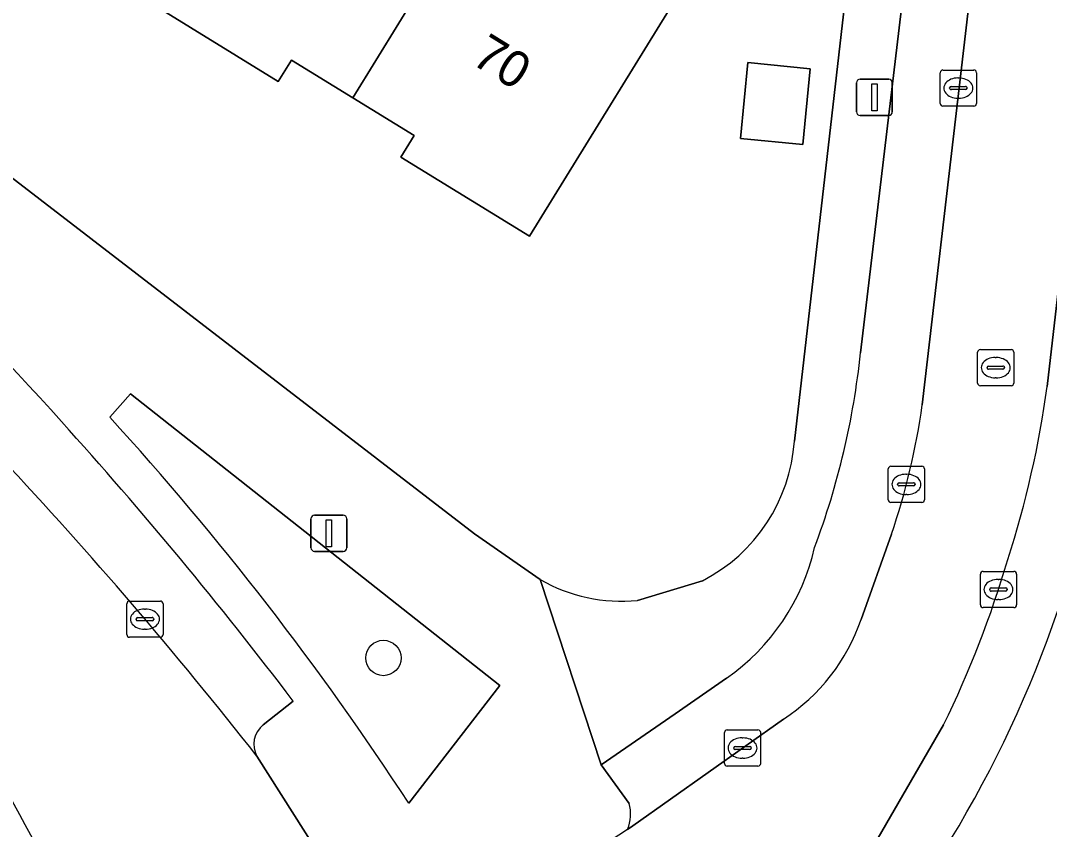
# Model space of a CAD drawing. Extents: x 161692 to 162379, y 380760 to 381678.
# Drawn here: x 161919.85 to 161948.28, y 381006.21 to 381028.56 of the extents above; entities that cross this region are included whole.
import ezdxf

# ---------------------------------------------------------------- set-up
doc = ezdxf.new("R2010")
doc.units = 0
for name, color, linetype in [('IMGEO_Boom', 7, 'Continuous'), ('IMGEO_Erf', 7, 'Continuous'), ('IMGEO_Groenvoorziening', 7, 'Continuous'), ('IMGEO_Kolk', 7, 'Continuous'), ('IMGEO_Lichtmast', 7, 'Continuous'), ('IMGEO_Pand', 7, 'Continuous'), ('IMGEO_Pand_nummerreeks', 7, 'Continuous'), ('IMGEO_Parkeervlak_open', 7, 'Continuous'), ('IMGEO_Rijbaan_lokaal_open', 7, 'Continuous'), ('IMGEO_Rioolput', 7, 'Continuous'), ('IMGEO_Voetpad_open', 7, 'Continuous')]:
    doc.layers.add(name, color=color, linetype=linetype)

msp = doc.modelspace()

# ---------------------------------------------------------------- linework, layer by layer
at = {"layer": 'IMGEO_Boom'}
msp.add_circle((161929.874, 381010.946), 0.489, dxfattribs=at)
at = {"layer": 'IMGEO_Erf'}
for points in [[(161941.233, 381016.938), (161944.934, 381049.22)], [(161918.09, 381043.966), (161920.768, 381042.317), (161920.378, 381041.684), (161922.995, 381040.073), (161925.41, 381038.587), (161926.13, 381039.756), (161928.914, 381038.042), (161934.18, 381034.801), (161934.766, 381035.752), (161940.015, 381032.521), (161938.727, 381030.429), (161933.91, 381022.602), (161930.356, 381024.789), (161930.723, 381025.385), (161929.03, 381026.427), (161927.333, 381027.472), (161926.969, 381026.881), (161923.395, 381029.081), (161919.818, 381031.283), (161920.176, 381031.865), (161918.558, 381032.86)], [(161916.42, 381026.67), (161932.395, 381014.373), (161934.208, 381013.114)], [(161936.895, 381012.539), (161938.695, 381013.082)]]:
    msp.add_lwpolyline(points, dxfattribs=at)
msp.add_lwpolyline([(161941.669, 381027.23), (161941.462, 381025.139), (161939.739, 381025.309), (161939.946, 381027.401)], close=True, dxfattribs=at)
for centre, radius, start, end in [((161936.529, 381017.271), 4.715, 297.3406, 355.954), ((161936.451, 381017.031), 4.514, 240.2007, 275.6418)]:
    msp.add_arc(centre, radius, start, end, dxfattribs=at)
at = {"layer": 'IMGEO_Groenvoorziening'}
msp.add_lwpolyline([(161930.575, 381006.93), (161933.096, 381010.186), (161922.886, 381018.248), (161922.313, 381017.602)], dxfattribs=at)
msp.add_arc((161860.947, 380961.56), 83.105, 33.08857, 42.40374, dxfattribs=at)
at = {"layer": 'IMGEO_Kolk'}
for p, q in [((161945.26, 381026.272), (161945.26, 381027.124)), ((161945.335, 381027.198), (161946.187, 381027.198)), ((161946.261, 381027.124), (161946.261, 381026.272)), ((161945.519, 381026.692), (161945.519, 381026.704)), ((161945.562, 381026.741), (161945.96, 381026.741)), ((161945.748, 381026.978), (161945.773, 381026.978)), ((161946.003, 381026.704), (161946.003, 381026.692)), ((161945.957, 381026.655), (161945.559, 381026.655)), ((161945.771, 381026.418), (161945.746, 381026.418)), ((161946.187, 381026.198), (161945.335, 381026.198)), ((161943.899, 381016.244), (161944.751, 381016.244)), ((161943.824, 381015.318), (161943.824, 381016.17)), ((161944.312, 381016.024), (161944.337, 381016.024)), ((161944.825, 381016.17), (161944.825, 381015.318)), ((161944.083, 381015.738), (161944.083, 381015.75)), ((161944.521, 381015.701), (161944.123, 381015.701)), ((161944.126, 381015.787), (161944.524, 381015.787)), ((161944.567, 381015.75), (161944.567, 381015.738)), ((161944.335, 381015.464), (161944.31, 381015.464)), ((161944.751, 381015.244), (161943.899, 381015.244)), ((161946.443, 381013.338), (161947.295, 381013.338)), ((161946.368, 381012.412), (161946.368, 381013.264)), ((161946.856, 381013.118), (161946.881, 381013.118)), ((161947.369, 381013.264), (161947.369, 381012.412)), ((161946.627, 381012.832), (161946.627, 381012.844)), ((161947.065, 381012.795), (161946.667, 381012.795)), ((161946.67, 381012.881), (161947.068, 381012.881)), ((161947.111, 381012.844), (161947.111, 381012.832)), ((161922.861, 381012.519), (161923.713, 381012.519)), ((161946.879, 381012.558), (161946.854, 381012.558)), ((161922.786, 381011.593), (161922.786, 381012.445)), ((161923.274, 381012.299), (161923.299, 381012.299)), ((161923.787, 381012.445), (161923.787, 381011.593)), ((161947.295, 381012.338), (161946.443, 381012.338)), ((161923.045, 381012.013), (161923.045, 381012.025)), ((161923.483, 381011.976), (161923.085, 381011.976)), ((161923.088, 381012.062), (161923.486, 381012.062)), ((161923.529, 381012.025), (161923.529, 381012.013)), ((161923.297, 381011.739), (161923.272, 381011.739)), ((161923.713, 381011.519), (161922.861, 381011.519)), ((161939.297, 381008.031), (161939.297, 381008.883)), ((161939.372, 381008.957), (161940.224, 381008.957)), ((161940.298, 381008.883), (161940.298, 381008.031)), ((161939.785, 381008.737), (161939.81, 381008.737)), ((161939.556, 381008.451), (161939.556, 381008.463)), ((161939.994, 381008.414), (161939.596, 381008.414)), ((161939.599, 381008.5), (161939.997, 381008.5)), ((161940.04, 381008.463), (161940.04, 381008.451)), ((161940.224, 381007.957), (161939.372, 381007.957)), ((161939.808, 381008.177), (161939.783, 381008.177))]:
    msp.add_line(p, q, dxfattribs=at)
for points in [[(161945.26, 381026.272), (161945.26, 381027.124)], [(161945.335, 381027.198), (161946.187, 381027.198)], [(161946.261, 381027.124), (161946.261, 381026.272)], [(161946.187, 381026.198), (161945.335, 381026.198)], [(161943.899, 381016.244), (161944.751, 381016.244)], [(161943.824, 381015.318), (161943.824, 381016.17)], [(161944.825, 381016.17), (161944.825, 381015.318)], [(161944.751, 381015.244), (161943.899, 381015.244)], [(161946.443, 381013.338), (161947.295, 381013.338)], [(161946.368, 381012.412), (161946.368, 381013.264)], [(161947.369, 381013.264), (161947.369, 381012.412)], [(161922.861, 381012.519), (161923.713, 381012.519)], [(161922.786, 381011.593), (161922.786, 381012.445)], [(161923.787, 381012.445), (161923.787, 381011.593)], [(161947.295, 381012.338), (161946.443, 381012.338)], [(161923.713, 381011.519), (161922.861, 381011.519)], [(161939.297, 381008.031), (161939.297, 381008.883)], [(161939.372, 381008.957), (161940.224, 381008.957)], [(161940.298, 381008.883), (161940.298, 381008.031)], [(161940.224, 381007.957), (161939.372, 381007.957)]]:
    msp.add_lwpolyline(points, dxfattribs=at)
for centre, radius, start, end in [((161945.337, 381027.122), 0.0765, 91.552, 178.448), ((161945.337, 381027.122), 0.0765, 91.552, 178.448), ((161946.185, 381027.122), 0.0765, 1.552, 88.448), ((161946.185, 381027.122), 0.0765, 1.552, 88.448), ((161945.559, 381026.701), 0.0403, 85.8775, 175.7526), ((161945.964, 381026.703), 0.0386, 1.7309, 96.639), ((161945.556, 381026.691), 0.0366, 178.938, 274.7102), ((161945.96, 381026.698), 0.043, 264.8664, 352.4533), ((161945.337, 381026.274), 0.0765, 181.552, 268.448), ((161945.337, 381026.274), 0.0765, 181.552, 268.448), ((161946.185, 381026.274), 0.0765, 271.552, 358.448), ((161946.185, 381026.274), 0.0765, 271.552, 358.448), ((161943.901, 381016.168), 0.0765, 91.552, 178.448), ((161943.901, 381016.168), 0.0765, 91.552, 178.448), ((161944.749, 381016.168), 0.0765, 1.552, 88.448), ((161944.749, 381016.168), 0.0765, 1.552, 88.448), ((161944.123, 381015.747), 0.0403, 85.8775, 175.7526), ((161944.12, 381015.737), 0.0366, 178.938, 274.7102), ((161944.524, 381015.744), 0.043, 264.8664, 352.4533), ((161944.528, 381015.749), 0.0386, 1.7309, 96.639), ((161943.901, 381015.32), 0.0765, 181.552, 268.448), ((161943.901, 381015.32), 0.0765, 181.552, 268.448), ((161944.749, 381015.32), 0.0765, 271.552, 358.448), ((161944.749, 381015.32), 0.0765, 271.552, 358.448), ((161946.445, 381013.262), 0.0765, 91.552, 178.448), ((161946.445, 381013.262), 0.0765, 91.552, 178.448), ((161947.293, 381013.262), 0.0765, 1.552, 88.448), ((161947.293, 381013.262), 0.0765, 1.552, 88.448), ((161946.667, 381012.841), 0.0403, 85.8775, 175.7526), ((161946.664, 381012.831), 0.0366, 178.938, 274.7102), ((161947.068, 381012.838), 0.043, 264.8664, 352.4533), ((161947.072, 381012.843), 0.0386, 1.7309, 96.639), ((161922.863, 381012.443), 0.0765, 91.552, 178.448), ((161922.863, 381012.443), 0.0765, 91.552, 178.448), ((161923.711, 381012.443), 0.0765, 1.552, 88.448), ((161923.711, 381012.443), 0.0765, 1.552, 88.448), ((161946.445, 381012.414), 0.0765, 181.552, 268.448), ((161946.445, 381012.414), 0.0765, 181.552, 268.448), ((161947.293, 381012.414), 0.0765, 271.552, 358.448), ((161947.293, 381012.414), 0.0765, 271.552, 358.448), ((161923.085, 381012.022), 0.0403, 85.8775, 175.7526), ((161923.082, 381012.012), 0.0366, 178.938, 274.7102), ((161923.486, 381012.019), 0.043, 264.8664, 352.4533), ((161923.49, 381012.024), 0.0386, 1.7309, 96.639), ((161922.863, 381011.595), 0.0765, 181.552, 268.448), ((161922.863, 381011.595), 0.0765, 181.552, 268.448), ((161923.711, 381011.595), 0.0765, 271.552, 358.448), ((161923.711, 381011.595), 0.0765, 271.552, 358.448), ((161939.374, 381008.881), 0.0765, 91.552, 178.448), ((161939.374, 381008.881), 0.0765, 91.552, 178.448), ((161940.222, 381008.881), 0.0765, 1.552, 88.448), ((161940.222, 381008.881), 0.0765, 1.552, 88.448), ((161939.596, 381008.46), 0.0403, 85.8775, 175.7526), ((161939.593, 381008.45), 0.0366, 178.938, 274.7102), ((161939.997, 381008.457), 0.043, 264.8664, 352.4533), ((161940.001, 381008.462), 0.0386, 1.7309, 96.639), ((161939.374, 381008.033), 0.0765, 181.552, 268.448), ((161939.374, 381008.033), 0.0765, 181.552, 268.448), ((161940.222, 381008.033), 0.0765, 271.552, 358.448), ((161940.222, 381008.033), 0.0765, 271.552, 358.448)]:
    msp.add_arc(centre, radius, start, end, dxfattribs=at)
for centre, major_axis, ratio, start_param, end_param in [((161945.747, 381026.698), (-0.387, 0.002), 0.722429, 4.712389, 7.853982), ((161945.772, 381026.698), (-0.39, 0.002), 0.717154, 1.570796, 4.712389), ((161944.311, 381015.744), (-0.387, 0.002), 0.722429, 4.712389, 7.853982), ((161944.336, 381015.744), (-0.39, 0.002), 0.717154, 1.570796, 4.712389), ((161946.855, 381012.838), (-0.387, 0.002), 0.722429, 4.712389, 7.853982), ((161946.88, 381012.838), (-0.39, 0.002), 0.717154, 1.570796, 4.712389), ((161923.273, 381012.019), (-0.387, 0.002), 0.722429, 4.712389, 7.853982), ((161923.298, 381012.019), (-0.39, 0.002), 0.717154, 1.570796, 4.712389), ((161939.784, 381008.457), (-0.387, 0.002), 0.722429, 4.712389, 7.853982), ((161939.809, 381008.457), (-0.39, 0.002), 0.717154, 1.570796, 4.712389)]:
    msp.add_ellipse(centre, major_axis=major_axis, ratio=ratio, start_param=start_param, end_param=end_param, dxfattribs=at)
at = {"layer": 'IMGEO_Lichtmast'}
for p, q in [((161942.946, 381026.043), (161942.946, 381026.843)), ((161942.946, 381026.843), (161942.946, 381026.043)), ((161943.046, 381026.943), (161943.836, 381026.943)), ((161943.836, 381026.943), (161943.046, 381026.943)), ((161943.936, 381026.843), (161943.936, 381026.043)), ((161943.936, 381026.043), (161943.936, 381026.843)), ((161943.836, 381025.943), (161943.046, 381025.943)), ((161943.046, 381025.943), (161943.836, 381025.943)), ((161927.873, 381013.993), (161927.873, 381014.793)), ((161927.873, 381014.793), (161927.873, 381013.993)), ((161927.973, 381014.893), (161928.763, 381014.893)), ((161928.763, 381014.893), (161927.973, 381014.893)), ((161928.863, 381014.793), (161928.863, 381013.993)), ((161928.863, 381013.993), (161928.863, 381014.793)), ((161928.763, 381013.893), (161927.973, 381013.893)), ((161927.973, 381013.893), (161928.763, 381013.893))]:
    msp.add_line(p, q, dxfattribs=at)
for points in [[(161943.366, 381026.818), (161943.516, 381026.818), (161943.516, 381026.068), (161943.366, 381026.068), (161943.366, 381026.818)], [(161928.293, 381014.768), (161928.443, 381014.768), (161928.443, 381014.018), (161928.293, 381014.018), (161928.293, 381014.768)]]:
    msp.add_lwpolyline(points, dxfattribs=at)
for centre, start, end in [((161943.046, 381026.843), 90, 180), ((161943.046, 381026.843), 90, 180), ((161943.836, 381026.843), 0, 90), ((161943.836, 381026.843), 360, 90), ((161943.046, 381026.043), 180, 270), ((161943.046, 381026.043), 180, 270), ((161943.836, 381026.043), 270, 0), ((161943.836, 381026.043), 270, 0), ((161927.973, 381014.793), 90, 180), ((161927.973, 381014.793), 90, 180), ((161928.763, 381014.793), 0, 90), ((161928.763, 381014.793), 360, 90), ((161927.973, 381013.993), 180, 270), ((161927.973, 381013.993), 180, 270), ((161928.763, 381013.993), 270, 0), ((161928.763, 381013.993), 270, 0)]:
    msp.add_arc(centre, 0.1, start, end, dxfattribs=at)
at = {"layer": 'IMGEO_Pand'}
for points in [[(161929.03, 381026.427), (161933.478, 381033.66), (161934.18, 381034.801), (161928.914, 381038.042), (161927.231, 381035.309), (161923.395, 381029.081), (161926.969, 381026.881), (161927.333, 381027.472)], [(161929.03, 381026.427), (161930.723, 381025.385), (161930.356, 381024.789), (161933.91, 381022.602), (161938.727, 381030.429), (161940.015, 381032.521), (161934.766, 381035.752), (161934.18, 381034.801), (161933.478, 381033.66)], [(161939.739, 381025.309), (161941.462, 381025.139), (161941.669, 381027.23), (161939.946, 381027.401)]]:
    msp.add_lwpolyline(points, close=True, dxfattribs=at)
at = {"layer": 'IMGEO_Parkeervlak_open'}
for points in [[(161951.537, 381047.312), (161948.215, 381018.454)], [(161944.762, 381017.945), (161947.774, 381043.773)], [(161947.216, 381043.338), (161945.922, 381043.47), (161943.058, 381019.379)], [(161943.072, 381012.012), (161943.909, 381014.364)], [(161939.355, 381010.387), (161937.932, 381009.403)], [(161926.556, 381009.098), (161927.383, 381009.756)], [(161937.932, 381009.403), (161935.896, 381007.996), (161936.668, 381006.927)], [(161936.622, 381006.207), (161936.769, 381006.303), (161940.927, 381009.257)], [(161945.352, 381009.095), (161943.208, 381005.381), (161942.657, 381004.695)]]:
    msp.add_lwpolyline(points, dxfattribs=at)
for centre, radius, start, end in [((161864.92, 380967.493), 75.109, 41.72193, 52.60698), ((161921.34, 381021.666), 21.838, 339.4468, 353.9891), ((161920.823, 381022.181), 27.645, 342.0648, 352.2521), ((161926.044, 381020.512), 18.893, 341.0111, 352.1923), ((161835.077, 380939.743), 115.854, 37.18005, 42.14298), ((161918.063, 381022.636), 32.167, 324.8168, 349.7493), ((161827.755, 380930.818), 125.378, 38.12777, 43.08627), ((161935.896, 381015.343), 6.044, 304.9176, 347.1549), ((161919.329, 381021.808), 28.962, 333.9621, 343.676), ((161938.019, 381013.733), 5.338, 303.0064, 341.1861), ((161926.972, 381008.562), 0.678, 127.8558, 209.5243), ((161935.576, 381006.635), 1.13, 337.7251, 14.9638)]:
    msp.add_arc(centre, radius, start, end, dxfattribs=at)
at = {"layer": 'IMGEO_Rijbaan_lokaal_open'}
for points in [[(161948.215, 381018.454), (161951.537, 381047.312), (161951.635, 381048.212), (161953.839, 381067.124), (161953.854, 381067.335), (161950.519, 381067.711), (161950.49, 381067.484), (161948.346, 381048.6), (161948.302, 381048.297), (161947.774, 381043.773), (161944.762, 381017.945)], [(161943.909, 381014.364), (161943.072, 381012.012)], [(161940.927, 381009.257), (161936.769, 381006.303), (161936.622, 381006.207), (161934.308, 381004.695), (161936.815, 381000.124), (161941.404, 381003.678)], [(161942.657, 381004.695), (161943.208, 381005.381), (161945.352, 381009.095)], [(161934.471, 380993.653), (161934.07, 380994.382), (161933.313, 380995.907), (161931.122, 381000), (161929.423, 381003.387), (161929.063, 381003.993), (161926.382, 381008.228)]]:
    msp.add_lwpolyline(points, dxfattribs=at)
for centre, radius, start, end in [((161920.823, 381022.181), 27.645, 342.0648, 352.2521), ((161926.044, 381020.512), 18.893, 341.0111, 352.1923), ((161827.755, 380930.818), 125.378, 38.12777, 43.08627), ((161885.32, 380987.728), 39.338, 26.8121, 41.8408), ((161919.329, 381021.808), 28.962, 333.9621, 343.676), ((161938.019, 381013.733), 5.338, 303.0064, 341.1861)]:
    msp.add_arc(centre, radius, start, end, dxfattribs=at)
at = {"layer": 'IMGEO_Rioolput'}
for p, q in [((161946.293, 381018.544), (161946.293, 381019.396)), ((161946.368, 381019.47), (161947.22, 381019.47)), ((161947.294, 381019.396), (161947.294, 381018.544)), ((161946.781, 381019.25), (161946.806, 381019.25)), ((161946.552, 381018.964), (161946.552, 381018.976)), ((161946.99, 381018.927), (161946.592, 381018.927)), ((161946.595, 381019.013), (161946.993, 381019.013)), ((161947.036, 381018.976), (161947.036, 381018.964)), ((161947.22, 381018.47), (161946.368, 381018.47)), ((161946.804, 381018.69), (161946.779, 381018.69))]:
    msp.add_line(p, q, dxfattribs=at)
for points in [[(161946.293, 381018.544), (161946.293, 381019.396)], [(161946.368, 381019.47), (161947.22, 381019.47)], [(161947.294, 381019.396), (161947.294, 381018.544)], [(161947.22, 381018.47), (161946.368, 381018.47)]]:
    msp.add_lwpolyline(points, dxfattribs=at)
for centre, radius, start, end in [((161946.37, 381019.394), 0.0765, 91.552, 178.448), ((161946.37, 381019.394), 0.0765, 91.552, 178.448), ((161947.218, 381019.394), 0.0765, 1.552, 88.448), ((161947.218, 381019.394), 0.0765, 1.552, 88.448), ((161946.592, 381018.973), 0.0403, 85.8775, 175.7526), ((161946.589, 381018.963), 0.0366, 178.938, 274.7102), ((161946.993, 381018.97), 0.043, 264.8664, 352.4533), ((161946.997, 381018.975), 0.0386, 1.7309, 96.639), ((161946.37, 381018.546), 0.0765, 181.552, 268.448), ((161946.37, 381018.546), 0.0765, 181.552, 268.448), ((161947.218, 381018.546), 0.0765, 271.552, 358.448), ((161947.218, 381018.546), 0.0765, 271.552, 358.448)]:
    msp.add_arc(centre, radius, start, end, dxfattribs=at)
for centre, major_axis, ratio, start_param, end_param in [((161946.78, 381018.97), (-0.387, 0.002), 0.722429, 4.712389, 7.853982), ((161946.805, 381018.97), (-0.39, 0.002), 0.717154, 1.570796, 4.712389)]:
    msp.add_ellipse(centre, major_axis=major_axis, ratio=ratio, start_param=start_param, end_param=end_param, dxfattribs=at)
at = {"layer": 'IMGEO_Voetpad_open'}
for points in [[(161957.191, 381155.412), (161956.388, 381149.129), (161956.162, 381145.456), (161954.88, 381134.431), (161954.037, 381127.184), (161953.476, 381122.354), (161952.893, 381117.344), (161952.318, 381112.4), (161951.753, 381107.539), (161951.18, 381102.61), (161950.594, 381097.573), (161950.03, 381092.727), (161949.327, 381086.68), (161948.751, 381081.721), (161948.175, 381076.772), (161947.611, 381071.919), (161947.025, 381066.879), (161946.46, 381062.027), (161945.855, 381056.821), (161945.65, 381055.374), (161944.934, 381049.22), (161941.233, 381016.938)], [(161943.058, 381019.379), (161945.922, 381043.47), (161947.216, 381043.338)], [(161936.668, 381006.927), (161935.896, 381007.996), (161934.208, 381013.114), (161932.395, 381014.373), (161916.42, 381026.67)], [(161922.313, 381017.602), (161922.886, 381018.248), (161933.096, 381010.186), (161930.575, 381006.93)], [(161934.208, 381013.114), (161935.896, 381007.996), (161937.932, 381009.403), (161939.355, 381010.387)], [(161938.695, 381013.082), (161936.895, 381012.539)], [(161927.383, 381009.756), (161926.556, 381009.098)], [(161926.382, 381008.228), (161929.063, 381003.993), (161929.506, 381004.223), (161931.726, 381000), (161933.756, 380996.137), (161933.313, 380995.907), (161934.07, 380994.382), (161934.471, 380993.653), (161939.336, 380985.302)]]:
    msp.add_lwpolyline(points, dxfattribs=at)
for centre, radius, start, end in [((161864.92, 380967.493), 75.109, 41.72193, 52.60698), ((161921.34, 381021.666), 21.838, 339.4468, 353.9891), ((161860.947, 380961.56), 83.105, 33.08857, 42.40374), ((161835.077, 380939.743), 115.854, 37.18005, 42.14298), ((161936.529, 381017.271), 4.715, 297.3406, 355.954), ((161918.063, 381022.636), 32.167, 324.8168, 349.7493), ((161885.32, 380987.728), 39.338, 26.8121, 41.8408), ((161935.896, 381015.343), 6.044, 304.9176, 347.1549), ((161936.451, 381017.031), 4.514, 240.2007, 275.6418), ((161926.972, 381008.562), 0.678, 127.8558, 209.5243), ((161935.576, 381006.635), 1.13, 337.7251, 14.9638)]:
    msp.add_arc(centre, radius, start, end, dxfattribs=at)

# ---------------------------------------------------------------- texts
at = {"layer": 'IMGEO_Pand_nummerreeks'}
msp.add_text('70', height=1, rotation=328.3387, dxfattribs=at).set_placement((161932.265, 381027.398))

doc.saveas('drawing.dxf')
